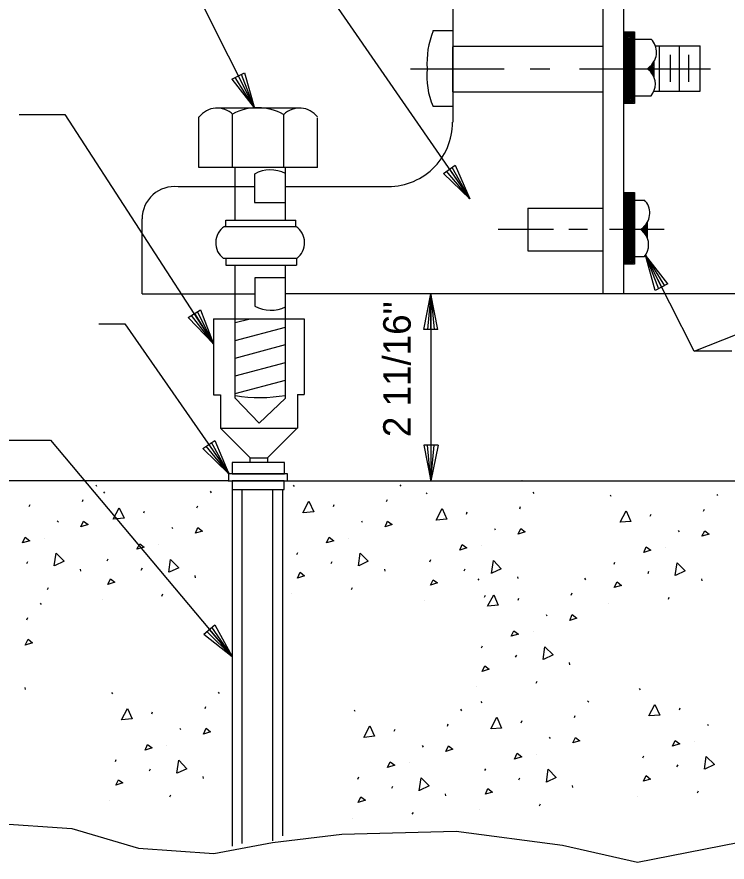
# Model space of a CAD drawing. Extents: x 12.3 to 19.6, y 18.8 to 29.6.
# Drawn here: x 13.484 to 15.033, y 21.66 to 23.505 of the extents above; entities that cross this region are included whole.
import ezdxf

# ---------------------------------------------------------------- set-up
doc = ezdxf.new("R2010")
doc.units = 0
for name, color, linetype in [('BORD-LINE', 7, 'Continuous'), ('DETL-DIMS', 7, 'Continuous'), ('DETL-LINE', 7, 'Continuous'), ('DETL-PATT', 7, 'Continuous')]:
    doc.layers.add(name, color=color, linetype=linetype)

msp = doc.modelspace()

# ---------------------------------------------------------------- linework, layer by layer
at = {"layer": 'DETL-DIMS'}
for p, q in [((14.343, 23.3913), (14.5468, 23.3913)), ((14.6037, 23.3913), (14.6469, 23.3913)), ((14.7116, 23.3913), (14.9814, 23.3913)), ((14.8639, 23.3913), (14.9969, 23.3913)), ((13.9528, 23.3685), (13.9809, 23.3823)), ((13.9528, 23.3685), (14.0026, 23.3055)), ((14.0026, 23.3055), (13.9606, 23.3721)), ((13.9672, 23.3751), (14.0026, 23.3055)), ((14.0026, 23.3055), (13.9738, 23.3787)), ((13.9809, 23.3823), (14.0026, 23.3055)), ((14.4149, 23.1629), (14.4402, 23.1809)), ((14.4719, 23.1077), (14.4215, 23.1677)), ((14.4275, 23.1719), (14.4719, 23.1077)), ((14.4719, 23.1077), (14.4335, 23.1761)), ((14.4402, 23.1809), (14.4719, 23.1077)), ((14.4149, 23.1629), (14.4719, 23.1077)), ((14.6547, 23.0406), (14.5336, 23.0406)), ((14.7285, 23.0406), (14.6877, 23.0406)), ((14.8957, 23.0406), (14.777, 23.0406)), ((14.8903, 22.9147), (14.8549, 22.9843)), ((14.8765, 22.9076), (14.8549, 22.9843)), ((14.904, 22.9219), (14.8549, 22.9843)), ((14.8549, 22.9843), (14.8837, 22.9112)), ((14.8549, 22.9843), (14.8969, 22.9177)), ((14.904, 22.9219), (14.8765, 22.9076)), ((14.3718, 22.8224), (14.3874, 22.9003)), ((14.3874, 22.9003), (14.3795, 22.8224)), ((14.3868, 22.9003), (14.3868, 22.4922)), ((14.3874, 22.8224), (14.3874, 22.9003)), ((14.4024, 22.8224), (14.3874, 22.9003)), ((14.3874, 22.9003), (14.3945, 22.8224)), ((13.858, 22.8488), (13.8844, 22.8656)), ((13.9132, 22.7913), (13.8653, 22.853)), ((13.8713, 22.8572), (13.9132, 22.7913)), ((13.9132, 22.7913), (13.8779, 22.8614)), ((13.8844, 22.8656), (13.9132, 22.7913)), ((13.858, 22.8488), (13.9132, 22.7913)), ((14.4024, 22.8224), (14.3718, 22.8224)), ((13.8899, 22.5629), (13.9157, 22.5802)), ((13.9468, 22.5077), (13.909, 22.5761)), ((13.9157, 22.5802), (13.9468, 22.5077)), ((13.8899, 22.5629), (13.9468, 22.5077)), ((13.9468, 22.5077), (13.897, 22.5677)), ((13.903, 22.5712), (13.9468, 22.5077)), ((14.4029, 22.5701), (14.3718, 22.5701)), ((14.3718, 22.5701), (14.3874, 22.4922)), ((14.3874, 22.4922), (14.3795, 22.5701)), ((14.3874, 22.5701), (14.3874, 22.4922)), ((14.4029, 22.5701), (14.3874, 22.4922)), ((14.3874, 22.4922), (14.3945, 22.5701)), ((13.8917, 22.1576), (13.9157, 22.178)), ((13.954, 22.1085), (13.9097, 22.1726)), ((13.9157, 22.178), (13.954, 22.1085)), ((13.8917, 22.1576), (13.954, 22.1085)), ((13.954, 22.1085), (13.8983, 22.1631)), ((13.9037, 22.1679), (13.954, 22.1085))]:
    msp.add_line(p, q, dxfattribs=at)
for points in [[(13.4624, 23.9787), (13.87, 23.9787), (14.4719, 23.1077)], [(13.7676, 23.649), (13.8299, 23.649), (14.0026, 23.3055)], [(13.4894, 23.2918), (13.589, 23.2918), (13.9132, 22.7913)], [(14.9616, 22.775), (15.6312, 23.04)], [(15.0437, 22.775), (14.9616, 22.775), (14.8549, 22.9843)], [(13.6632, 22.835), (13.7196, 22.835), (13.9474, 22.5077)], [(13.4145, 22.5809), (13.5572, 22.5809), (13.954, 22.1085)]]:
    msp.add_lwpolyline(points, dxfattribs=at)
at = {"layer": 'DETL-LINE'}
for p, q in [((14.762, 24.5643), (14.762, 22.9003)), ((14.8075, 24.5643), (14.8075, 22.9003)), ((14.4347, 23.555), (14.4347, 23.275)), ((14.4347, 23.4417), (14.4347, 23.3403)), ((14.4347, 23.4404), (14.762, 23.4404)), ((14.4347, 23.3409), (14.4347, 23.4392)), ((14.8765, 23.4417), (14.9742, 23.4417)), ((14.8855, 23.3427), (14.8855, 23.4417)), ((14.9293, 23.3427), (14.9293, 23.4417)), ((14.9742, 23.3427), (14.9742, 23.4417)), ((14.8603, 23.3907), (14.8741, 23.4051)), ((14.8741, 23.3721), (14.8741, 23.4081)), ((14.91, 23.3631), (14.91, 23.4218)), ((14.9497, 23.3631), (14.9497, 23.4218)), ((14.8597, 23.3913), (14.8657, 23.3973)), ((14.8597, 23.3913), (14.8675, 23.3841)), ((14.8609, 23.3907), (14.8741, 23.4027)), ((14.8615, 23.3895), (14.8741, 23.4003)), ((14.8627, 23.3889), (14.8741, 23.3973)), ((14.8633, 23.3877), (14.8741, 23.3954)), ((14.8645, 23.3871), (14.8741, 23.3937)), ((14.8657, 23.3859), (14.8741, 23.3919)), ((14.8669, 23.3847), (14.8741, 23.3901)), ((14.8675, 23.3835), (14.8741, 23.3883)), ((14.8687, 23.3823), (14.8741, 23.3865)), ((14.8693, 23.3811), (14.8741, 23.3847)), ((14.8705, 23.3799), (14.8741, 23.3829)), ((14.8711, 23.3787), (14.8741, 23.3811)), ((14.8717, 23.3769), (14.8741, 23.3793)), ((14.8729, 23.3757), (14.8741, 23.3775)), ((14.8735, 23.3745), (14.8741, 23.3757)), ((14.8741, 23.3733), (14.8741, 23.3739)), ((14.4347, 23.3409), (14.762, 23.3409)), ((14.8735, 23.3427), (14.9742, 23.3427)), ((14.1045, 23.3055), (13.9204, 23.3055)), ((13.8809, 23.1761), (13.8809, 23.2864)), ((13.9546, 23.1761), (13.9546, 23.293)), ((14.0667, 23.1761), (14.0667, 23.2912)), ((14.1398, 23.1761), (14.1398, 23.2846)), ((14.1398, 23.1761), (13.8809, 23.1761)), ((13.9606, 23.061), (13.9606, 23.1761)), ((14.0133, 23.1761), (14.0133, 23.1755)), ((14.0703, 23.061), (14.0703, 23.1761)), ((14.0026, 23.1617), (14.0026, 23.0994)), ((13.8359, 23.1341), (14.0026, 23.1341)), ((14.0703, 23.1341), (14.2873, 23.1341)), ((14.0026, 23.0994), (14.0703, 23.0994)), ((14.5983, 23.0874), (14.762, 23.0874)), ((14.5983, 23.0874), (14.5983, 22.9938)), ((13.7574, 22.9003), (13.7574, 23.064)), ((13.9396, 23.0472), (13.9396, 23.061)), ((14.0925, 23.0472), (14.0925, 23.061)), ((14.8597, 23.0208), (14.8597, 23.0568)), ((14.8453, 23.04), (14.8597, 23.0544)), ((14.8453, 23.0406), (14.8513, 23.0466)), ((14.8453, 23.0406), (14.8525, 23.0328)), ((14.8459, 23.0395), (14.8597, 23.052)), ((14.8465, 23.0388), (14.8597, 23.0502)), ((14.8471, 23.0382), (14.8597, 23.0478)), ((14.8483, 23.0376), (14.8597, 23.0455)), ((14.8489, 23.0365), (14.8597, 23.0436)), ((14.8501, 23.0352), (14.8597, 23.0418)), ((14.8513, 23.034), (14.8597, 23.0395)), ((14.8531, 23.0328), (14.8597, 23.0376)), ((14.8537, 23.0311), (14.8597, 23.0352)), ((14.8549, 23.0298), (14.8597, 23.0335)), ((14.8555, 23.0286), (14.8597, 23.0316)), ((14.8567, 23.0275), (14.8597, 23.0298)), ((14.8573, 23.0262), (14.8597, 23.0281)), ((14.8579, 23.0251), (14.8597, 23.0262)), ((14.8585, 23.0238), (14.8597, 23.0251)), ((14.8591, 23.0226), (14.8597, 23.0238)), ((14.5983, 22.9938), (14.762, 22.9938)), ((13.9396, 22.9771), (13.9396, 22.9627)), ((13.9606, 22.8458), (13.9606, 22.9627)), ((14.0703, 22.8458), (14.0703, 22.9627)), ((14.0937, 22.9771), (14.0937, 22.9627)), ((14.0037, 22.8734), (14.0037, 22.9357)), ((14.0037, 22.9357), (14.0703, 22.9357)), ((14.762, 22.9112), (14.762, 22.9052)), ((13.7574, 22.9003), (14.0037, 22.9003)), ((16.4206, 22.9003), (14.0703, 22.9003)), ((13.9132, 22.8458), (14.1111, 22.8458)), ((13.9132, 22.8458), (13.9132, 22.6798)), ((13.9606, 22.8374), (13.9929, 22.8458)), ((13.9606, 22.6726), (13.9606, 22.8458)), ((14.0703, 22.6726), (14.0703, 22.8458)), ((14.1111, 22.8458), (14.1111, 22.6804)), ((13.9606, 22.7984), (14.0703, 22.8278)), ((13.9606, 22.7601), (14.0703, 22.7895)), ((13.9606, 22.7211), (14.0703, 22.7505)), ((13.9606, 22.6828), (14.0703, 22.7121)), ((13.9132, 22.6798), (13.9282, 22.6798)), ((13.9282, 22.6798), (13.9282, 22.6072)), ((14.0127, 22.618), (13.9606, 22.6726)), ((14.0127, 22.618), (14.0703, 22.6726)), ((14.0961, 22.6804), (14.1111, 22.6804)), ((14.0961, 22.6804), (14.0961, 22.6072)), ((13.9282, 22.6072), (14.0961, 22.6072)), ((13.9929, 22.5425), (13.9282, 22.6072)), ((14.0307, 22.5425), (14.0961, 22.6079)), ((13.9929, 22.5425), (14.0307, 22.5425)), ((13.9456, 22.4922), (13.2197, 22.4922)), ((13.945, 22.4922), (13.954, 22.4922)), ((14.0745, 22.4922), (15.2451, 22.4922)), ((14.5863, 22.4922), (14.5858, 22.4922)), ((14.6187, 22.4922), (14.6277, 22.4922)), ((13.954, 22.473), (13.954, 21.6949)), ((13.9749, 22.473), (13.9749, 21.7009)), ((14.0415, 22.473), (14.0415, 21.7063)), ((14.0637, 22.473), (14.0637, 21.7177))]:
    msp.add_line(p, q, dxfattribs=at)
for points in [[(14.3922, 23.474), (14.3922, 23.4746), (14.4353, 23.4746), (14.4353, 23.3092), (14.3922, 23.3092)], [(14.8075, 23.4722), (14.8315, 23.4722), (14.8315, 23.3158), (14.8075, 23.3158)], [(14.8075, 23.4698), (14.8291, 23.4698), (14.8291, 23.3182), (14.8075, 23.3182)], [(14.8075, 23.4674), (14.8274, 23.4674), (14.8274, 23.3205), (14.8075, 23.3205)], [(14.8075, 23.4656), (14.8249, 23.4656), (14.8249, 23.3224), (14.8075, 23.3224)], [(14.8075, 23.4632), (14.8225, 23.4632), (14.8225, 23.3248), (14.8075, 23.3248)], [(14.8075, 23.4614), (14.8208, 23.4614), (14.8208, 23.3265), (14.8075, 23.3265)], [(14.8075, 23.4591), (14.8184, 23.4591), (14.8184, 23.3289), (14.8075, 23.3289)], [(14.8075, 23.4566), (14.8165, 23.4566), (14.8165, 23.3313), (14.8075, 23.3313)], [(14.8075, 23.4548), (14.8141, 23.4548), (14.8141, 23.3332), (14.8075, 23.3332)], [(14.8075, 23.4524), (14.8118, 23.4524), (14.8118, 23.3355), (14.8075, 23.3355)], [(14.8075, 23.4501), (14.81, 23.4501), (14.81, 23.3373), (14.8075, 23.3373)], [(14.8315, 23.4561), (14.8675, 23.4561)], [(14.8675, 23.3319), (14.8315, 23.3319)], [(14.8075, 23.121), (14.8315, 23.121), (14.8315, 22.9651), (14.8075, 22.9651)], [(14.8075, 23.1191), (14.8291, 23.1191), (14.8291, 22.9675), (14.8075, 22.9675)], [(14.8075, 23.1167), (14.8274, 23.1167), (14.8274, 22.9693), (14.8075, 22.9693)], [(14.8075, 23.115), (14.8249, 23.115), (14.8249, 22.9717), (14.8075, 22.9717)], [(14.8075, 23.1126), (14.8225, 23.1126), (14.8225, 22.9741), (14.8075, 22.9741)], [(14.8075, 23.1101), (14.8208, 23.1101), (14.8208, 22.9759), (14.8075, 22.9759)], [(14.8075, 23.1084), (14.8184, 23.1084), (14.8184, 22.9783), (14.8075, 22.9783)], [(14.8075, 23.106), (14.8165, 23.106), (14.8165, 22.9801), (14.8075, 22.9801)], [(14.8075, 23.1041), (14.8141, 23.1041), (14.8141, 22.9825), (14.8075, 22.9825)], [(14.8075, 23.1017), (14.8118, 23.1017), (14.8118, 22.9848), (14.8075, 22.9848)], [(14.8075, 23.0994), (14.81, 23.0994), (14.81, 22.9867), (14.8075, 22.9867)], [(14.8315, 23.1054), (14.8315, 23.1054)], [(14.8315, 23.1047), (14.8531, 23.1047)], [(13.9396, 23.061), (14.0925, 23.061)], [(13.9366, 23.0472), (14.0931, 23.0472)], [(14.0942, 22.9771), (13.9348, 22.9771)], [(13.9396, 22.9627), (14.0937, 22.9627)], [(14.8525, 22.9807), (14.8315, 22.9807)], [(13.2197, 21.7633), (13.4337, 21.7453), (13.604, 21.7333), (13.7496, 21.6908), (13.9138, 21.6788), (14.0415, 21.7028), (14.1931, 21.7213), (14.4425, 21.7273), (14.6739, 21.6968), (14.8375, 21.6601), (15.0569, 21.7028), (15.1421, 21.7519), (15.2451, 21.783)]]:
    msp.add_lwpolyline(points, dxfattribs=at)
for points in [[(13.9929, 22.5425), (14.0307, 22.5425), (14.0307, 22.5323), (13.9929, 22.5323)], [(14.0678, 22.5323), (13.9534, 22.5323), (13.9534, 22.5077), (14.0678, 22.5077)], [(14.0745, 22.5077), (13.9456, 22.5077), (13.9456, 22.4922), (14.0745, 22.4922)], [(13.954, 22.473), (14.0673, 22.473), (14.0673, 22.4922), (13.954, 22.4922)]]:
    msp.add_lwpolyline(points, close=True, dxfattribs=at)
for centre, radius, start, end in [((14.5705, 23.4036), 0.192, 158.4431, 183.718), ((14.839, 23.4274), 0.0403, 311.8294, 44.8972), ((14.5479, 23.3761), 0.1697, 174.9233, 203.1757), ((14.8365, 23.3581), 0.0403, 319.9275, 40.3584), ((13.9209, 23.2561), 0.0494, 45.7869, 142.2633), ((14.0094, 23.1915), 0.1148, 60.5637, 118.4513), ((14.1008, 23.2561), 0.0494, 37.7367, 134.2131), ((14.2941, 23.2744), 0.1402, 267.1649, 0.195), ((14.0373, 23.1007), 0.0701, 62.0283, 119.7614), ((13.8274, 23.064), 0.0701, 83.0683, 180), ((14.8243, 23.0764), 0.0403, 311.8294, 44.8972), ((13.9609, 23.0117), 0.0431, 124.132, 233.0361), ((14.0686, 23.0117), 0.0431, 306.9639, 55.868), ((14.8218, 23.0071), 0.0403, 319.9275, 40.3584), ((14.0383, 22.9344), 0.0701, 240.2386, 297.0321), ((14.0149, 23.0185), 0.3445, 260.9589, 279.228)]:
    msp.add_arc(centre, radius, start, end, dxfattribs=at)
at = {"layer": 'DETL-PATT'}
for p, q in [((13.6561, 22.4837), (13.6579, 22.4808)), ((14.3196, 22.4837), (14.3214, 22.4808)), ((13.6729, 22.4682), (13.6752, 22.4652)), ((13.9054, 22.4693), (13.9078, 22.4663)), ((14.0865, 22.4826), (14.0888, 22.4796)), ((14.3772, 22.4663), (14.379, 22.4634)), ((14.6097, 22.4676), (14.6116, 22.4646)), ((13.6273, 22.4472), (13.6291, 22.4514)), ((14.2903, 22.4472), (14.2926, 22.4514)), ((14.7782, 22.4616), (14.78, 22.4586)), ((15.0108, 22.4622), (15.0126, 22.4598)), ((13.5111, 22.4358), (13.5128, 22.4406)), ((13.8767, 22.4334), (13.879, 22.4376)), ((14.1746, 22.4358), (14.1764, 22.4406)), ((14.581, 22.431), (14.5828, 22.4358)), ((14.982, 22.4262), (14.9838, 22.4304)), ((13.761, 22.4221), (13.7628, 22.4262)), ((14.4647, 22.4196), (14.4665, 22.4244)), ((14.8657, 22.4148), (14.8675, 22.4191)), ((13.5722, 22.4047), (13.5746, 22.4017)), ((13.8221, 22.3908), (13.8239, 22.3878)), ((14.2357, 22.4047), (14.2375, 22.4017)), ((14.5258, 22.3884), (14.5276, 22.3854)), ((14.9268, 22.3837), (14.9287, 22.3807)), ((13.5446, 22.3669), (13.5446, 22.3669)), ((14.2075, 22.3669), (14.2075, 22.3669)), ((13.7939, 22.3525), (13.7939, 22.3525)), ((14.0948, 22.3315), (14.0972, 22.3357)), ((14.4977, 22.3507), (14.4977, 22.3507)), ((14.8987, 22.3459), (14.8987, 22.3459)), ((13.6812, 22.3177), (13.6831, 22.3219)), ((14.385, 22.3153), (14.3874, 22.3202)), ((13.5062, 22.3117), (13.5081, 22.3159)), ((13.6225, 22.2992), (13.6231, 22.2949)), ((13.7556, 22.2973), (13.758, 22.3022)), ((14.1697, 22.3117), (14.1716, 22.3159)), ((14.286, 22.2992), (14.2866, 22.2949)), ((14.4599, 22.2955), (14.4617, 22.2998)), ((14.7866, 22.3105), (14.7884, 22.3147)), ((13.8725, 22.2854), (13.873, 22.2805)), ((14.5762, 22.2829), (14.5768, 22.2788)), ((14.8609, 22.2902), (14.8627, 22.2949)), ((14.4893, 22.2782), (14.4917, 22.2752)), ((14.7219, 22.2794), (14.7242, 22.2764)), ((14.9772, 22.2782), (14.9778, 22.274)), ((13.5506, 22.2548), (13.553, 22.259)), ((13.8005, 22.2404), (13.8024, 22.2452)), ((14.0835, 22.2464), (14.0835, 22.2464)), ((14.2141, 22.2548), (14.216, 22.259)), ((14.6931, 22.2428), (14.6955, 22.2476)), ((13.535, 22.2254), (13.5368, 22.2224)), ((13.6699, 22.2326), (13.6699, 22.2326)), ((14.3735, 22.2302), (14.3735, 22.2302)), ((14.5043, 22.2386), (14.5061, 22.2428)), ((14.5774, 22.232), (14.5792, 22.2362)), ((14.7746, 22.2254), (14.7746, 22.2254)), ((14.9053, 22.2338), (14.907, 22.238)), ((13.5062, 22.1889), (13.5081, 22.1936)), ((14.6385, 22.2003), (14.6403, 22.1973)), ((14.6103, 22.1625), (14.6103, 22.1625)), ((14.4977, 22.1277), (14.4994, 22.1319)), ((14.572, 22.1074), (14.5744, 22.1115)), ((14.6889, 22.0954), (14.6895, 22.0905)), ((13.5014, 22.0414), (13.5021, 22.0366)), ((14.4863, 22.0426), (14.4863, 22.0426)), ((14.617, 22.0504), (14.6187, 22.0552)), ((13.6909, 22.03), (13.6926, 22.027)), ((13.9234, 22.0312), (13.9252, 22.0282)), ((14.8411, 22.039), (14.8435, 22.036)), ((14.4964, 22.0108), (14.4983, 22.0078)), ((14.729, 22.012), (14.7315, 22.009)), ((13.7784, 21.9838), (13.7801, 21.9881)), ((13.8947, 21.9952), (13.8964, 21.9995)), ((14.2195, 21.9922), (14.2214, 21.9892)), ((14.4521, 21.9935), (14.4539, 21.9905)), ((14.9293, 21.9922), (14.931, 21.9971)), ((14.584, 21.9641), (14.5863, 21.9688)), ((14.7002, 21.9755), (14.7021, 21.9797)), ((13.8395, 21.9527), (13.8413, 21.9497)), ((14.307, 21.9455), (14.3089, 21.9503)), ((14.4233, 21.9568), (14.4252, 21.9617)), ((14.9904, 21.9611), (14.9922, 21.9581)), ((14.6451, 21.9329), (14.6475, 21.9299)), ((13.8113, 21.9143), (13.8113, 21.9143)), ((14.3682, 21.9143), (14.3706, 21.9113)), ((14.9622, 21.9233), (14.9622, 21.9233)), ((14.6176, 21.8952), (14.6176, 21.8952)), ((13.6992, 21.8796), (13.701, 21.8837)), ((14.3406, 21.8766), (14.3406, 21.8766)), ((14.8495, 21.8879), (14.8519, 21.8922)), ((13.7735, 21.8592), (13.7754, 21.8639)), ((14.5048, 21.8598), (14.5067, 21.8639)), ((14.9238, 21.8682), (14.9263, 21.8723)), ((13.8899, 21.8472), (13.8904, 21.8424)), ((14.2279, 21.8412), (14.2297, 21.8459)), ((14.5792, 21.84), (14.581, 21.8442)), ((14.3023, 21.8214), (14.304, 21.8256)), ((14.6955, 21.8274), (14.6961, 21.8232)), ((13.8179, 21.8022), (13.8198, 21.807)), ((14.4185, 21.8088), (14.4192, 21.8047)), ((14.8381, 21.8028), (14.8381, 21.8028)), ((14.9688, 21.8112), (14.9706, 21.8154)), ((13.6872, 21.7944), (13.6872, 21.7944)), ((14.6241, 21.783), (14.626, 21.7873)), ((14.3466, 21.7644), (14.349, 21.7687)), ((14.4934, 21.7747), (14.4934, 21.7747)), ((14.216, 21.756), (14.216, 21.756))]:
    msp.add_line(p, q, dxfattribs=at)
for points in [[(14.1081, 22.4226), (14.1212, 22.4478), (14.132, 22.4244), (14.1086, 22.4226)], [(13.6945, 22.4088), (13.7076, 22.4334), (13.7179, 22.4107), (13.695, 22.4088)], [(14.3988, 22.4064), (14.4119, 22.4316), (14.4222, 22.4088), (14.3988, 22.4064)], [(14.7998, 22.4017), (14.813, 22.4268), (14.8231, 22.4034), (14.7998, 22.4017)], [(13.6237, 22.3921), (13.6297, 22.4041), (13.6393, 22.3968), (13.6237, 22.3921)], [(14.2873, 22.3921), (14.2926, 22.4041), (14.3029, 22.3968), (14.2873, 22.3921)], [(13.8737, 22.3777), (13.879, 22.3903), (13.8893, 22.3824), (13.8737, 22.3777)], [(14.5774, 22.3759), (14.5833, 22.3878), (14.593, 22.3807), (14.5774, 22.3759)], [(14.9784, 22.3711), (14.9844, 22.3831), (14.9939, 22.3759), (14.9784, 22.3711)], [(13.4966, 22.3567), (13.5026, 22.3693), (13.5122, 22.3614), (13.4966, 22.3567)], [(13.746, 22.3429), (13.752, 22.3549), (13.7616, 22.3477), (13.746, 22.3429)], [(14.1596, 22.3567), (14.1656, 22.3693), (14.1752, 22.3614), (14.1596, 22.3567)], [(14.4503, 22.3405), (14.4557, 22.3531), (14.4659, 22.3459), (14.4503, 22.3405)], [(14.8513, 22.3357), (14.8567, 22.3483), (14.8669, 22.3405), (14.8513, 22.3357)], [(13.5656, 22.3063), (13.5697, 22.3345), (13.5871, 22.3165), (13.5662, 22.3063)], [(13.8155, 22.2925), (13.8191, 22.3202), (13.8371, 22.3022), (13.8161, 22.2925)], [(14.2291, 22.3063), (14.2327, 22.3345), (14.2507, 22.3165), (14.2297, 22.3063)], [(14.5192, 22.2902), (14.5234, 22.3183), (14.5408, 22.3003), (14.5198, 22.2908)], [(14.9203, 22.2854), (14.9244, 22.3135), (14.9418, 22.2955), (14.9209, 22.2854)], [(14.0961, 22.2799), (14.1021, 22.2925), (14.1116, 22.2848), (14.0961, 22.2799)], [(13.6825, 22.2662), (13.6885, 22.2782), (13.698, 22.271), (13.6825, 22.2662)], [(14.3862, 22.2644), (14.3922, 22.2764), (14.4018, 22.2692), (14.3862, 22.2644)], [(14.7871, 22.259), (14.7931, 22.2715), (14.8028, 22.2638), (14.7871, 22.259)], [(14.5108, 22.2188), (14.5241, 22.2434), (14.5342, 22.2206), (14.5114, 22.2188)], [(14.6901, 22.1876), (14.6955, 22.2003), (14.7056, 22.1924), (14.6901, 22.1876)], [(14.5624, 22.1529), (14.5684, 22.1649), (14.578, 22.1576), (14.5624, 22.1529)], [(13.5026, 22.1337), (13.5086, 22.1463), (13.5182, 22.1385), (13.5026, 22.1337)], [(14.632, 22.1025), (14.6355, 22.1301), (14.6535, 22.1121), (14.6325, 22.1025)], [(14.4988, 22.0761), (14.5048, 22.0881), (14.5144, 22.081), (14.4988, 22.0761)], [(14.8627, 21.9791), (14.8759, 22.0042), (14.8867, 21.9808), (14.8633, 21.9791)], [(13.7124, 21.9707), (13.7256, 21.9952), (13.7358, 21.9725), (13.7124, 21.9707)], [(14.5181, 21.9508), (14.5312, 21.9761), (14.5414, 21.9527), (14.5187, 21.9508)], [(13.891, 21.9395), (13.897, 21.9521), (13.9067, 21.9443), (13.891, 21.9395)], [(14.2411, 21.9323), (14.2543, 21.9575), (14.2645, 21.9347), (14.2417, 21.9323)], [(14.6967, 21.9203), (14.7026, 21.9323), (14.7122, 21.9251), (14.6967, 21.9203)], [(13.764, 21.9047), (13.7694, 21.9167), (13.7795, 21.9096), (13.764, 21.9047)], [(14.4198, 21.9017), (14.4257, 21.9137), (14.4353, 21.9066), (14.4198, 21.9017)], [(14.9143, 21.9131), (14.9203, 21.9257), (14.9298, 21.9179), (14.9143, 21.9131)], [(14.5696, 21.8849), (14.5756, 21.8976), (14.5852, 21.8897), (14.5696, 21.8849)], [(13.8329, 21.8544), (13.8371, 21.8826), (13.8545, 21.8639), (13.8335, 21.8544)], [(14.2926, 21.8663), (14.2986, 21.8789), (14.3083, 21.8718), (14.2926, 21.8663)], [(14.9838, 21.8628), (14.9874, 21.8909), (15.0054, 21.8729), (14.9844, 21.8628)], [(14.6391, 21.8346), (14.6427, 21.8628), (14.6601, 21.8448), (14.6391, 21.8346)], [(13.6999, 21.828), (13.7059, 21.84), (13.7154, 21.8328), (13.6999, 21.828)], [(14.3616, 21.816), (14.3658, 21.8442), (14.3832, 21.8262), (14.3622, 21.8166)], [(14.8508, 21.8364), (14.8567, 21.8489), (14.8663, 21.8412), (14.8508, 21.8364)], [(14.5061, 21.8082), (14.5114, 21.8208), (14.5217, 21.813), (14.5061, 21.8082)], [(14.2285, 21.7903), (14.2345, 21.8022), (14.2447, 21.795), (14.2285, 21.7903)]]:
    msp.add_lwpolyline(points, dxfattribs=at)

# ---------------------------------------------------------------- texts
at = {"layer": 'BORD-LINE'}
msp.add_text('2 11/16"', height=0.06, rotation=90, dxfattribs=at).set_placement((14.3431, 22.5876))

doc.saveas('drawing.dxf')
